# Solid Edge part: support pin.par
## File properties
Author: Sarvanan
Template: sync ansi part.par
Last saved by: CADCIM
Revision: 6
Application: Solid Edge
Accuracy: 0.990
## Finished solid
Body 1: solid body, 9 faces, 8 edges, 0 vertices.
  Faces by surface: plane 4, cylinder 3, cone 2
  Edges by curve: circle 8
Bounding box of the edges (mm): 6.350 x 6.350 x 66.675, from (12.0753, 27.1097, -66.675) to (18.4253, 33.4597, 0).
Cylindrical faces by radius (mm): R2.413 x2, R3.175 x1
Conical faces (half-angle, radius in mm at the cone's reference point): 44.9733 deg R1.6517 x2
Planar faces by outward normal: +z 2, -z 2
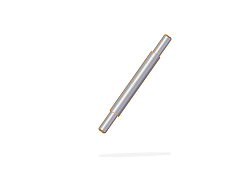
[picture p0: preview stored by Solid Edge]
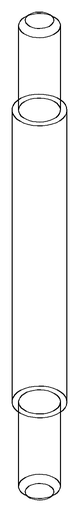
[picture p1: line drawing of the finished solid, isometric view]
